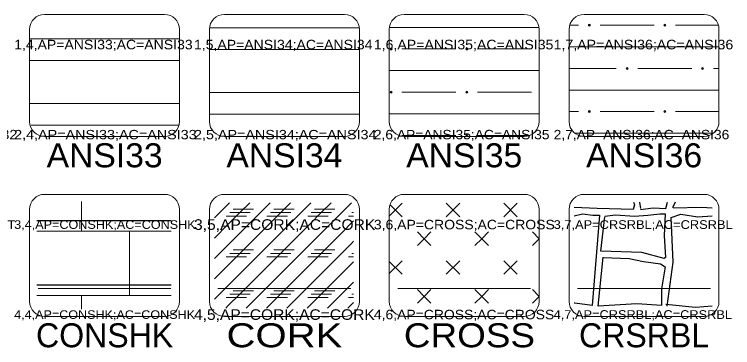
# Model space of a CAD drawing. Extents: x 95935 to 95946.4, y 95971.2 to 95974.7.
# Drawn here: x 95936.835 to 95939.231, y 95973.621 to 95974.732 of the extents above; entities that cross this region are included whole.
import ezdxf
from ezdxf.enums import TextEntityAlignment as Align

# ---------------------------------------------------------------- set-up
doc = ezdxf.new("R2010")
doc.units = 0
doc.header["$LTSCALE"] = 0.013
doc.header["$PDMODE"] = 32
doc.header["$PDSIZE"] = 0.0065
for name, color, linetype, lineweight in [('1', 7, 'Continuous', 13), ('25', 7, 'Continuous', 13), ('6', 7, 'Continuous', 13), ('63', 7, 'Continuous', 13)]:
    doc.layers.add(name, color=color, linetype=linetype, lineweight=lineweight)
doc.layers.add('20', color=7, linetype='Continuous')

msp = doc.modelspace()

# ---------------------------------------------------------------- linework, layer by layer
at = {"layer": '1'}
for p, q in [((95936.9357, 95974.7318), (95937.3357, 95974.7318)), ((95937.5357, 95974.7318), (95937.9357, 95974.7318)), ((95938.1357, 95974.7318), (95938.5357, 95974.7318)), ((95938.7357, 95974.7318), (95939.1357, 95974.7318)), ((95936.8857, 95974.3747), (95936.8857, 95974.6818)), ((95937.3857, 95974.6818), (95937.3857, 95974.3747)), ((95937.4857, 95974.3747), (95937.4857, 95974.6818)), ((95937.9857, 95974.6818), (95937.9857, 95974.3747)), ((95938.0857, 95974.3747), (95938.0857, 95974.6818)), ((95938.5857, 95974.6818), (95938.5857, 95974.3747)), ((95938.6857, 95974.3747), (95938.6857, 95974.6818)), ((95939.1857, 95974.6818), (95939.1857, 95974.3747)), ((95937.3357, 95974.3247), (95936.9357, 95974.3247)), ((95937.9357, 95974.3247), (95937.5357, 95974.3247)), ((95938.5357, 95974.3247), (95938.1357, 95974.3247)), ((95939.1357, 95974.3247), (95938.7357, 95974.3247)), ((95936.9357, 95974.1318), (95937.3357, 95974.1318)), ((95937.5357, 95974.1318), (95937.9357, 95974.1318)), ((95938.1357, 95974.1318), (95938.5357, 95974.1318)), ((95938.7357, 95974.1318), (95939.1357, 95974.1318)), ((95936.8857, 95973.7747), (95936.8857, 95974.0818)), ((95937.3857, 95974.0818), (95937.3857, 95973.7747)), ((95937.4857, 95973.7747), (95937.4857, 95974.0818)), ((95937.9857, 95974.0818), (95937.9857, 95973.7747)), ((95938.0857, 95973.7747), (95938.0857, 95974.0818)), ((95938.5857, 95974.0818), (95938.5857, 95973.7747)), ((95938.6857, 95973.7747), (95938.6857, 95974.0818)), ((95939.1857, 95974.0818), (95939.1857, 95973.7747)), ((95937.3357, 95973.7247), (95936.9357, 95973.7247)), ((95937.9357, 95973.7247), (95937.5357, 95973.7247)), ((95938.5357, 95973.7247), (95938.1357, 95973.7247)), ((95939.1357, 95973.7247), (95938.7357, 95973.7247))]:
    msp.add_line(p, q, dxfattribs=at)
for centre, start, end in [((95936.9357, 95974.6818), 90, 180), ((95937.3357, 95974.6818), 0, 90), ((95937.5357, 95974.6818), 90, 180), ((95937.9357, 95974.6818), 0, 90), ((95938.1357, 95974.6818), 90, 180), ((95938.5357, 95974.6818), 0, 90), ((95938.7357, 95974.6818), 90, 180), ((95939.1357, 95974.6818), 0, 90), ((95936.9357, 95974.3747), 180, 270), ((95937.3357, 95974.3747), 270, 0), ((95937.5357, 95974.3747), 180, 270), ((95937.9357, 95974.3747), 270, 0), ((95938.1357, 95974.3747), 180, 270), ((95938.5357, 95974.3747), 270, 0), ((95938.7357, 95974.3747), 180, 270), ((95939.1357, 95974.3747), 270, 0), ((95936.9357, 95974.0818), 90, 180), ((95937.3357, 95974.0818), 0, 90), ((95937.5357, 95974.0818), 90, 180), ((95937.9357, 95974.0818), 0, 90), ((95938.1357, 95974.0818), 90, 180), ((95938.5357, 95974.0818), 0, 90), ((95938.7357, 95974.0818), 90, 180), ((95939.1357, 95974.0818), 0, 90), ((95936.9357, 95973.7747), 180, 270), ((95937.3357, 95973.7747), 270, 0), ((95937.5357, 95973.7747), 180, 270), ((95937.9357, 95973.7747), 270, 0), ((95938.1357, 95973.7747), 180, 270), ((95938.5357, 95973.7747), 270, 0), ((95938.7357, 95973.7747), 180, 270), ((95939.1357, 95973.7747), 270, 0)]:
    msp.add_arc(centre, 0.05, start, end, dxfattribs=at)
at = {"layer": '25'}
for p, q in [((95937.3569, 95973.8178), (95936.9141, 95973.8178)), ((95937.9569, 95973.8178), (95937.5141, 95973.8178)), ((95938.5569, 95973.8178), (95938.1141, 95973.8178)), ((95939.1569, 95973.8178), (95938.7141, 95973.8178)), ((95938.7141, 95973.8178), (95939.1569, 95973.8178))]:
    msp.add_line(p, q, dxfattribs=at)
at = {"layer": '6'}
for p, q in [((95937.4867, 95974.6869), (95937.9847, 95974.6869)), ((95938.087, 95974.6884), (95938.5844, 95974.6884)), ((95938.6884, 95974.6956), (95938.7171, 95974.6956)), ((95938.6884, 95974.6956), (95938.7171, 95974.6956)), ((95938.7891, 95974.6956), (95938.9691, 95974.6956)), ((95938.7891, 95974.6956), (95938.9691, 95974.6956)), ((95939.0411, 95974.6956), (95939.183, 95974.6956)), ((95939.0411, 95974.6956), (95939.183, 95974.6956)), ((95936.8857, 95974.6505), (95937.3857, 95974.6505)), ((95937.4857, 95974.6149), (95937.9857, 95974.6149)), ((95938.1279, 95974.6164), (95938.3079, 95974.6164)), ((95938.3799, 95974.6164), (95938.5599, 95974.6164)), ((95938.6857, 95974.6236), (95939.1857, 95974.6236)), ((95936.8857, 95974.5785), (95937.3857, 95974.5785)), ((95938.0857, 95974.5444), (95938.5857, 95974.5444)), ((95938.6857, 95974.5516), (95938.7891, 95974.5516)), ((95938.7891, 95974.5516), (95938.8431, 95974.5516)), ((95938.9151, 95974.5516), (95939.0951, 95974.5516)), ((95939.1671, 95974.5516), (95939.1857, 95974.5516)), ((95937.4857, 95974.4709), (95937.9857, 95974.4709)), ((95938.1279, 95974.4724), (95938.3079, 95974.4724)), ((95938.3799, 95974.4724), (95938.5599, 95974.4724)), ((95938.6857, 95974.4796), (95939.1857, 95974.4796)), ((95936.8857, 95974.4345), (95937.3857, 95974.4345)), ((95937.4857, 95974.3989), (95937.9857, 95974.3989)), ((95938.0857, 95974.4004), (95938.5857, 95974.4004)), ((95938.6857, 95974.4076), (95938.7171, 95974.4076)), ((95938.6857, 95974.4076), (95938.7171, 95974.4076)), ((95938.7891, 95974.4076), (95938.9691, 95974.4076)), ((95938.7891, 95974.4076), (95938.9691, 95974.4076)), ((95939.0411, 95974.4076), (95939.1857, 95974.4076)), ((95939.0411, 95974.4076), (95939.1857, 95974.4076)), ((95936.8907, 95974.3625), (95937.3833, 95974.3625)), ((95938.1279, 95974.3284), (95938.3079, 95974.3284)), ((95938.3799, 95974.3284), (95938.5543, 95974.3284)), ((95938.7059, 95974.3356), (95939.1655, 95974.3356)), ((95937.0591, 95974.0089), (95937.0591, 95974.1085)), ((95937.5136, 95974.0652), (95937.5522, 95974.1038)), ((95937.5871, 95974.0708), (95937.6201, 95974.1038)), ((95937.621, 95974.0369), (95937.688, 95974.1038)), ((95937.655, 95974.0029), (95937.7511, 95974.0991)), ((95937.7511, 95974.0991), (95937.7558, 95974.1038)), ((95937.7851, 95974.0652), (95937.8237, 95974.1038)), ((95937.8586, 95974.0708), (95937.8916, 95974.1038)), ((95937.8926, 95974.0369), (95937.9595, 95974.1038)), ((95938.0857, 95974.0595), (95938.1286, 95974.1024)), ((95938.0887, 95974.0971), (95938.1286, 95974.0572)), ((95938.2754, 95974.0572), (95938.3206, 95974.1024)), ((95938.2754, 95974.1024), (95938.3206, 95974.0572)), ((95938.4674, 95974.0572), (95938.5126, 95974.1024)), ((95938.4674, 95974.1024), (95938.5126, 95974.0572)), ((95937.5021, 95974.0537), (95937.5136, 95974.0652)), ((95937.5475, 95974.0312), (95937.5871, 95974.0708)), ((95937.5871, 95974.0708), (95937.5532, 95974.0708)), ((95937.5758, 95974.0821), (95937.5645, 95974.0821)), ((95937.6323, 95974.0821), (95937.5758, 95974.0821)), ((95937.621, 95974.0708), (95937.5871, 95974.0708)), ((95937.7568, 95974.0708), (95937.6889, 95974.0708)), ((95937.6889, 95973.969), (95937.7851, 95974.0652)), ((95937.7681, 95974.0821), (95937.7002, 95974.0821)), ((95937.819, 95974.0312), (95937.8586, 95974.0708)), ((95937.8586, 95974.0708), (95937.8247, 95974.0708)), ((95937.8473, 95974.0821), (95937.836, 95974.0821)), ((95937.9039, 95974.0821), (95937.8473, 95974.0821)), ((95937.8926, 95974.0708), (95937.8586, 95974.0708)), ((95937.9667, 95974.0708), (95937.9604, 95974.0708)), ((95937.5984, 95974.0595), (95937.5418, 95974.0595)), ((95937.6097, 95974.0595), (95937.5984, 95974.0595)), ((95937.7455, 95974.0595), (95937.6776, 95974.0595)), ((95937.8699, 95974.0595), (95937.8134, 95974.0595)), ((95937.8813, 95974.0595), (95937.8699, 95974.0595)), ((95937.9265, 95974.0029), (95937.9667, 95974.0431)), ((95937.9667, 95974.0595), (95937.9491, 95974.0595)), ((95937.5021, 95973.9858), (95937.5475, 95974.0312)), ((95937.5814, 95973.9973), (95937.621, 95974.0369)), ((95937.7229, 95973.9351), (95937.819, 95974.0312)), ((95937.853, 95973.9973), (95937.8926, 95974.0369)), ((95936.9102, 95974.0089), (95937.3582, 95974.0089)), ((95937.2191, 95973.7942), (95937.2191, 95974.0089)), ((95937.5021, 95973.9179), (95937.5814, 95973.9973)), ((95937.6154, 95973.9633), (95937.655, 95974.0029)), ((95937.7568, 95973.9011), (95937.853, 95973.9973)), ((95937.8869, 95973.9633), (95937.9265, 95974.0029)), ((95938.1794, 95974.0064), (95938.202, 95973.9838)), ((95938.202, 95973.9838), (95938.2246, 95974.0064)), ((95938.3714, 95974.0064), (95938.394, 95973.9838)), ((95938.394, 95973.9838), (95938.4166, 95974.0064)), ((95938.5634, 95974.0064), (95938.586, 95973.9838)), ((95937.6493, 95973.9294), (95937.6889, 95973.969)), ((95937.9208, 95973.9294), (95937.9604, 95973.969)), ((95937.9604, 95973.969), (95937.9667, 95973.9753)), ((95938.1794, 95973.9612), (95938.202, 95973.9838)), ((95938.202, 95973.9838), (95938.2246, 95973.9612)), ((95938.3714, 95973.9612), (95938.394, 95973.9838)), ((95938.394, 95973.9838), (95938.4166, 95973.9612)), ((95938.5634, 95973.9612), (95938.586, 95973.9838)), ((95937.5192, 95973.8672), (95937.6154, 95973.9633)), ((95937.6323, 95973.9464), (95937.5645, 95973.9464)), ((95937.7115, 95973.9464), (95937.7002, 95973.9464)), ((95937.7681, 95973.9464), (95937.7115, 95973.9464)), ((95937.7907, 95973.8672), (95937.8869, 95973.9633)), ((95937.9039, 95973.9464), (95937.836, 95973.9464)), ((95937.6097, 95973.9237), (95937.5418, 95973.9237)), ((95937.621, 95973.9351), (95937.5532, 95973.9351)), ((95937.5532, 95973.8332), (95937.6493, 95973.9294)), ((95937.7342, 95973.9237), (95937.6776, 95973.9237)), ((95937.6833, 95973.8955), (95937.7229, 95973.9351)), ((95937.7229, 95973.9351), (95937.6889, 95973.9351)), ((95937.7568, 95973.9351), (95937.7229, 95973.9351)), ((95937.7455, 95973.9237), (95937.7342, 95973.9237)), ((95937.8813, 95973.9237), (95937.8134, 95973.9237)), ((95937.8926, 95973.9351), (95937.8247, 95973.9351)), ((95937.8247, 95973.8332), (95937.9208, 95973.9294)), ((95937.9667, 95973.9237), (95937.9491, 95973.9237)), ((95937.9667, 95973.9351), (95937.9604, 95973.9351)), ((95937.5871, 95973.7993), (95937.6833, 95973.8955)), ((95937.7172, 95973.8615), (95937.7568, 95973.9011)), ((95937.8586, 95973.7993), (95937.9548, 95973.8955)), ((95937.9548, 95973.8955), (95937.9667, 95973.9074)), ((95938.0857, 95973.8675), (95938.1286, 95973.9104)), ((95938.0857, 95973.9081), (95938.1286, 95973.8652)), ((95938.2754, 95973.8652), (95938.3206, 95973.9104)), ((95938.2754, 95973.9104), (95938.3206, 95973.8652)), ((95938.4674, 95973.8652), (95938.5126, 95973.9104)), ((95938.4674, 95973.9104), (95938.5126, 95973.8652)), ((95937.5021, 95973.8501), (95937.5192, 95973.8672)), ((95937.621, 95973.7653), (95937.7172, 95973.8615)), ((95937.7511, 95973.8276), (95937.7907, 95973.8672)), ((95937.5136, 95973.7936), (95937.5532, 95973.8332)), ((95937.6759, 95973.7523), (95937.7511, 95973.8276)), ((95937.7851, 95973.7936), (95937.8247, 95973.8332)), ((95937.8926, 95973.7653), (95937.9667, 95973.8395)), ((95937.5475, 95973.7597), (95937.5871, 95973.7993)), ((95937.5871, 95973.7993), (95937.5532, 95973.7993)), ((95937.5758, 95973.8106), (95937.5645, 95973.8106)), ((95937.6323, 95973.8106), (95937.5758, 95973.8106)), ((95937.621, 95973.7993), (95937.5871, 95973.7993)), ((95937.7568, 95973.7993), (95937.6889, 95973.7993)), ((95937.7681, 95973.8106), (95937.7002, 95973.8106)), ((95937.819, 95973.7597), (95937.8586, 95973.7993)), ((95937.8586, 95973.7993), (95937.8247, 95973.7993)), ((95937.8473, 95973.8106), (95937.836, 95973.8106)), ((95937.9039, 95973.8106), (95937.8473, 95973.8106)), ((95937.8926, 95973.7993), (95937.8586, 95973.7993)), ((95937.9667, 95973.7993), (95937.9604, 95973.7993)), ((95938.1794, 95973.8144), (95938.202, 95973.7918)), ((95938.202, 95973.7918), (95938.2246, 95973.8144)), ((95938.3714, 95973.8144), (95938.394, 95973.7918)), ((95938.394, 95973.7918), (95938.4166, 95973.8144)), ((95938.5634, 95973.8144), (95938.586, 95973.7918)), ((95936.9102, 95973.7942), (95937.3582, 95973.7942)), ((95937.0591, 95973.7486), (95937.0591, 95973.7942)), ((95937.5021, 95973.7821), (95937.5136, 95973.7936)), ((95937.5984, 95973.788), (95937.5418, 95973.788)), ((95937.6097, 95973.788), (95937.5984, 95973.788)), ((95937.7455, 95973.788), (95937.6776, 95973.788)), ((95937.7438, 95973.7523), (95937.7851, 95973.7936)), ((95937.8699, 95973.788), (95937.8134, 95973.788)), ((95937.8813, 95973.788), (95937.8699, 95973.788)), ((95937.9667, 95973.788), (95937.9491, 95973.788)), ((95938.1794, 95973.7692), (95938.202, 95973.7918)), ((95938.202, 95973.7918), (95938.2246, 95973.7692)), ((95938.3714, 95973.7692), (95938.394, 95973.7918)), ((95938.394, 95973.7918), (95938.4166, 95973.7692)), ((95938.5634, 95973.7692), (95938.586, 95973.7918)), ((95937.5401, 95973.7523), (95937.5475, 95973.7597)), ((95937.608, 95973.7523), (95937.621, 95973.7653)), ((95937.8116, 95973.7523), (95937.819, 95973.7597)), ((95937.8796, 95973.7523), (95937.8926, 95973.7653)), ((95937.9474, 95973.7523), (95937.9667, 95973.7716))]:
    msp.add_line(p, q, dxfattribs=at)
at = {"layer": '6', "lineweight": 25}
for p, q in [((95938.9201, 95974.1056), (95938.9237, 95974.0842)), ((95939.0391, 95974.1056), (95939.0306, 95974.0867)), ((95936.9102, 95974.0447), (95937.3582, 95974.0447)), ((95936.9102, 95973.83), (95937.3582, 95973.83))]:
    msp.add_line(p, q, dxfattribs=at)
for points in [[(95938.9009, 95974.1056), (95938.9039, 95974.0966), (95938.8989, 95974.0817), (95938.7796, 95974.0842), (95938.702, 95974.0883)], [(95938.9237, 95974.0817), (95938.966, 95974.0867), (95939.0083, 95974.0842), (95939.0141, 95974.1056)], [(95939.0331, 95974.0867), (95939.1276, 95974.0892), (95939.1627, 95974.0866)], [(95938.702, 95974.0601), (95938.7299, 95974.0668), (95938.7647, 95974.0619), (95938.787, 95974.0619), (95938.7622, 95973.7618), (95938.705, 95973.7692), (95938.702, 95973.7689)], [(95938.8044, 95974.0594), (95938.8401, 95974.0634), (95938.9039, 95974.0594), (95938.9486, 95974.0619), (95938.9884, 95974.0668), (95939.0058, 95974.0668), (95939.0033, 95973.9949), (95939.0074, 95973.9212), (95939.0033, 95973.918), (95938.9287, 95973.9379), (95938.792, 95973.9428), (95938.8044, 95974.0569)], [(95939.0132, 95973.7593), (95939.0331, 95973.9056), (95939.0257, 95974.0544), (95939.0581, 95974.066), (95939.1152, 95974.0569), (95939.1627, 95974.06)], [(95938.7997, 95973.9212), (95938.8865, 95973.918), (95938.9337, 95973.9081), (95938.9909, 95973.9007), (95939.0058, 95973.8907), (95938.9934, 95973.8163), (95938.9934, 95973.7618), (95938.9113, 95973.7667), (95938.7821, 95973.7593), (95938.7997, 95973.9221)], [(95939.1627, 95973.7589), (95939.1077, 95973.7543), (95939.0083, 95973.7643)]]:
    msp.add_lwpolyline(points, dxfattribs=at)
at = {"layer": '6'}
for p in [(95938.7531, 95974.6956), (95939.0051, 95974.6956), (95938.0919, 95974.6164), (95938.3439, 95974.6164), (95938.8791, 95974.5516), (95939.1311, 95974.5516), (95938.0919, 95974.4724), (95938.3439, 95974.4724), (95938.7531, 95974.4076), (95939.0051, 95974.4076), (95938.3439, 95974.3284)]:
    msp.add_point(p, dxfattribs=at)

# ---------------------------------------------------------------- texts
at = {"layer": '20'}
for s, width, p in [('ANSI33', 1.05, (95937.1359, 95974.222)), ('ANSI34', 1.05, (95937.7357, 95974.222)), ('ANSI35', 1.05, (95938.3357, 95974.222)), ('ANSI36', 1.05, (95938.9358, 95974.222)), (' CORK ', 1.25, (95937.7358, 95973.622)), (' CROSS', 1.15, (95938.3359, 95973.622))]:
    msp.add_text(s, height=0.08, dxfattribs=dict(at, width=width)).set_placement(p, align=Align.CENTER)
for s, p in [('CONSHK', (95937.1359, 95973.622)), ('CRSRBL', (95938.9358, 95973.622))]:
    msp.add_text(s, height=0.08, dxfattribs=at).set_placement(p, align=Align.CENTER)
at = {"layer": '63'}
for s, height, width, p in [('1,4,AP=ANSI33;AC=ANSI33', 0.0318, 1.1, (95936.8341, 95974.6152)), ('1,5,AP=ANSI34;AC=ANSI34', 0.0318, 1.1, (95937.4341, 95974.6152)), ('1,6,AP=ANSI35;AC=ANSI35', 0.032, 1.1, (95938.0341, 95974.6151)), ('1,7,AP=ANSI36;AC=ANSI36', 0.032, 1.1, (95938.6341, 95974.6151)), ('2,3,AP=ANSI32;AC=ANSI32', 0.0312, 1.15, (95936.2341, 95974.3155)), ('2,4,AP=ANSI33;AC=ANSI33', 0.0311, 1.15, (95936.8341, 95974.3155)), ('2,5,AP=ANSI34;AC=ANSI34', 0.0311, 1.15, (95937.4341, 95974.3155)), ('2,6,AP=ANSI35;AC=ANSI35', 0.0313, 1.1, (95938.0341, 95974.3154)), ('2,7,AP=ANSI36;AC=ANSI36', 0.0313, 1.1, (95938.6341, 95974.3154)), ('3,3,AP=CONCRT;AC=CONCRT', 0.0285, 1.1, (95936.2341, 95974.0168)), ('3,4,AP=CONSHK;AC=CONSHK', 0.0286, 1.1, (95936.8341, 95974.0168)), ('3,5,AP=CORK;AC=CORK', 0.0354, 1.1, (95937.4341, 95974.0134)), ('3,6,AP=CROSS;AC=CROSS', 0.0317, 1.1, (95938.0341, 95974.0152)), ('3,7,AP=CRSRBL;AC=CRSRBL', 0.0291, 1.1, (95938.6341, 95974.0165)), ('4,4,AP=CONSHK;AC=CONSHK', 0.0285, 1.1, (95936.8341, 95973.7168)), ('4,5,AP=CORK;AC=CORK', 0.0353, 1.1, (95937.4341, 95973.7134)), ('4,6,AP=CROSS;AC=CROSS', 0.0316, 1.1, (95938.0341, 95973.7153)), ('4,7,AP=CRSRBL;AC=CRSRBL', 0.029, 1.1, (95938.6341, 95973.7166))]:
    msp.add_text(s, height=height, dxfattribs=dict(at, width=width)).set_placement(p)

doc.saveas('drawing.dxf')
